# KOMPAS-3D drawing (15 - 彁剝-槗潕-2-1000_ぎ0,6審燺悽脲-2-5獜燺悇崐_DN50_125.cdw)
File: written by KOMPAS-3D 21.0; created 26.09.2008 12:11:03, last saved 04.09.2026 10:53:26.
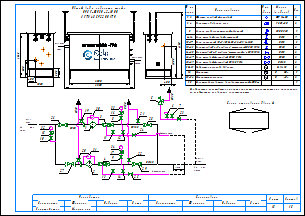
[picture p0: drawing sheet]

Sheets 1-2: A3, landscape

Document properties: Наименование: Макро:21; Автор: RaskoAdmin; Форматы листов документа: 2xA3; Полное имя файла: \\UR38nt01\Departments\КТО\КБ ПУРДГ\Заявки\Прайс-лист на типовые шкафы ГРПШ\ПРДГ_стандарт_20_03_2026\ПРДГ с РДНК\ПРДГ-ШУЭО-2-1000_до0,6МПа_Рвых-2-5кПа_РДНК_DN50_125.cdw

Title block, sheet 1: Наименование: Пункт учета газа / ПУГ-Ш-400-Р / ЛГТИ.485922.001ТУ; designation: ЛГТИ.03.4411141; sheet number: 1; Количество листов документа: 2; organisation: ООО "ЭЛЬСТЕР Газэлектроника"; Форматы листов документа: A3; stored path: C:\Рабочие документы\Компас\ПУГ\Схема.cdw; Разработал: Устинов; Проверил: Кошкин; Утвердил: Кошкин
Title block, sheet 2: sheet number: 2; stored path: D:\Рабочие документы\Заявки\ПУРДГ\ПУРДГ-ШУЭО-2-100-Р 4411220.cdw; designation, second copy: ЛГТИ.03.4411141-

Views: Вид 1, Вид 2
Referenced files: wcvoit.frw
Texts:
  Normal
  Вход
  газа
  PDI
  Выход
  Р=     кПа
  DN125
  DN50
  DN20
  Импульс DN15
  ≥5DN
  HYSWLongFangSong
  № на
  схеме
  Усл.
  обозн.
  Марка
  (модель)
  Кол.
  Фильтр газовый фланцевый
  ФГ 16-50
  Регулятор давления газа
  РДНК-50
  Клапан предохранительный сбросной
  КПС DN20
  Кран шаровой газовый латунный
  DN15
  Кран кнопочный VE-РАСКО-НЗ-1,6-G1/2-М20
  Кран шаровой "под приварку" штуцерный DN20 PN16
  Кран шаровой "под приварку" штуцерный п/п DN15 PN16
  Кран шаровой фланцевый DN50 PN16
  Кран шаровой фланцевый DN125 PN16
  Индикатор перепада давления
  Delta 15
  Манометр
  Манометр-напоромер
  Электрообогреватель взрывозащищенный 400Вт
  0...     МПа
  0...     кПа
  Общий вид и габариты шкафа
  ПРДГ-ШУЭО-2-1000
  Выход газа
  Вход газа
  Схема открывания дверей
  Р=        МПа
  logo-rasko-ge.png
  Предприятие изготовитель может заменять комплектующие на аналогичные,
  не ухудшающие заявленных характеристик.
  Должность
  Конструктор
  Фамилия
  Подпись
  Дата
  Согласовано
  Максимкин
  Лист
  Листов
  POLYLINE_STYLE_0.18_RGB_0_0_0
  POLYLINE_STYLE_0.50_RGB_0_0_0
  POLYLINE_STYLE_0.34_RGB_0_0_0
  PHANTOM_RGB_0_0_0_SC_1_THICK_0.18
  K5LT_THIN_RGB_0_0_0_THICK_0.18
  K5LT32769_RGB_0_0_0_THICK_0.18
  K5LT12_RGB_0_0_0_SC_1_THICK_0.18
  K5LT_DASHED_RGB_0_0_0_SC_1_THICK_0.18
  ACISOTGL_RGB_0_0_0_SC_0.8_THICK_0.25
  CONTINUOUS_RGB_0_127_31_THICK_0.3
  CONTINUOUS_RGB_0_0_255_THICK_0.35
  CONTINUOUS_RGB_255_0_0_THICK_0.35
  POLYLINE_STYLE_0.25_RGB_0_0_0
  CONTINUOUS_RGB_0_0_0_THICK_0.5
  POLYLINE_STYLE_0.35_RGB_0_0_255
  CONTINUOUS_RGB_0_0_0_THICK_0.4
  CONTINUOUS_RGB_0_0_0_THICK_0.35
  Без оформления
Dimensions and other numbers on the sheet: 1; 2; 3; 4; 5; 10; 27; 28; 29; 23; 8; 12; 19; 20; 21; 22; 25; 24; 30; 31; 15; 16; 26; 6; 7; 11; 14; 13; 33; 1, 2; 3, 4; 6-14; 9; 15-17; 18-23; 24-25; 26-27; 28-29; 30-31; 32; 33-34; 35; 400; 1050; 500; 305; 2500; 1565; 2800; 17; 34; 1000; 4130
